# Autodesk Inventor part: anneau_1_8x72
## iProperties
Created: 2011-01
Part Number: anneau_1_8x72
Document SubType Name: Modeling
Designer: eric
Density: 1 g/cm^3
Mass: 0.575595 g
Surface Area: 12.791 cm^2
Volume: 0.575595 cm^3
Author: eric
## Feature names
1. Base1
